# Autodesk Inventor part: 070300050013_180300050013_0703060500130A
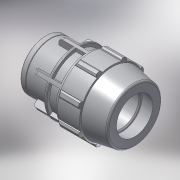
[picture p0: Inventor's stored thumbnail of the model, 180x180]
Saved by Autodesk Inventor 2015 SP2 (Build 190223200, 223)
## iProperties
Created: 2017-02
Part Number: 070300050013_180300050013_0703060500130A
Material: PVC-Piping
Description: PLASSON FEMALE ADAPTOR 50-1.1/4"
Document SubType Name: Modeling
Designer: KIM
Mass: 92.6774 g
Surface Area: 199.44 cm^2
Volume: 66.1981 cm^3
Density: 1.4 g/cm^3
Appearance: Smooth - White
Author: KIM
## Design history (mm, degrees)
derived "07030.ipt"
feature "Solid1::07030.ipt"
tag "TaggingFeature1"
body "Solid1"
other parameters: "d4" = 17.57143, "d5" = 30.75, "d7" = 96, "d9" = 17.57143, "d11" = 3.51429, "d12" = 76.8, "d13" = 120 deg, "d14" = 75, "d15" = 10 deg, "d16" = 86.4, "d18" = 2.5, "d19" = 35 deg, "d20" = 17.5 deg, "d21" = 89.28, "d23" = 0, "d25" = 360 deg, "d27" = 1.92, "d34" = 4.8, "d35" = 36.9, "d36" = 0, "d42" = 30.75, "d43" = 2.88, "d46" = 1.5, "d49" = 93, "d51" = 123, "d53" = 1, "d55" = 360 deg, "d61" = 25, "d63" = 38.952, "d64" = 41, "d65" = 4.8, "d66" = 0.5, "d67" = 1, "d68" = 7.5, "d69" = 69.12, "d70" = 2.4, "E_" = 96, "H_" = 123, "l_" = 93, "l_2" = 25, "Rp_" = 38.952
